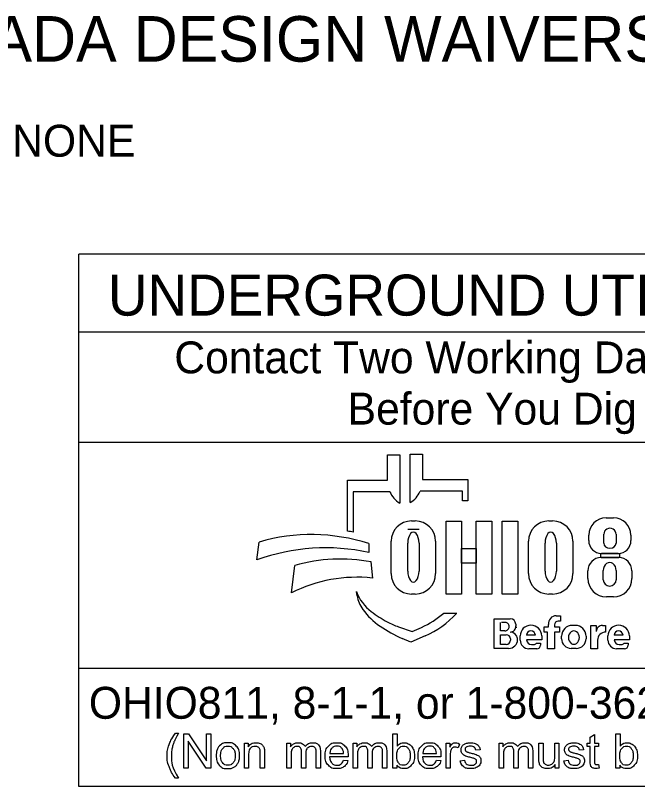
# Model space of a CAD drawing. Extents: x 0 to 34, y 0 to 22.
# Drawn here: x 2.1 to 4.831, y 2.143 to 5.529 of the extents above; entities that cross this region are included whole.
import ezdxf

# ---------------------------------------------------------------- set-up
doc = ezdxf.new("R2010")
doc.units = 0
for name, color, linetype in [('Default', 7, 'Continuous'), ('SH_Data', 7, 'Continuous'), ('SH_Text', 7, 'Continuous')]:
    doc.layers.add(name, color=color, linetype=linetype)

msp = doc.modelspace()

# ---------------------------------------------------------------- linework, layer by layer
at = {"layer": 'SH_Data'}
for p, q in [((2.3775, 2.1428), (2.3775, 4.4803)), ((6.6275, 4.4803), (2.3775, 4.4803)), ((2.3775, 4.1387), (6.6275, 4.1387)), ((2.3775, 3.6553), (6.6275, 3.6553)), ((6.6275, 2.6607), (2.3775, 2.6607)), ((6.6275, 2.1428), (2.3775, 2.1428))]:
    msp.add_line(p, q, dxfattribs=at)
at = {"layer": 'SH_Text'}
for p, q in [((3.7335, 3.4883), (3.7335, 3.5998)), ((3.7335, 3.5998), (3.7872, 3.5998)), ((3.7872, 3.5998), (3.7872, 3.3877)), ((3.8329, 3.39), (3.8329, 3.6021)), ((3.8329, 3.6021), (3.8865, 3.6021)), ((3.8865, 3.6021), (3.8865, 3.4906)), ((3.5576, 3.2644), (3.5576, 3.4883)), ((3.5576, 3.4883), (3.7335, 3.4883)), ((3.8865, 3.4906), (4.0857, 3.4906)), ((4.0857, 3.4906), (4.0857, 3.3968)), ((3.5828, 3.4369), (3.5828, 3.26)), ((3.7439, 3.4369), (3.5828, 3.4369)), ((4.0625, 3.4392), (3.8761, 3.4392)), ((4.0625, 3.3968), (4.0625, 3.4392)), ((4.0857, 3.3968), (4.0625, 3.3968)), ((4.6931, 3.3231), (4.7258, 3.3231)), ((3.8385, 3.3091), (3.8551, 3.3091)), ((4.4416, 3.3091), (4.4581, 3.3091)), ((3.8718, 3.2721), (3.822, 3.2721)), ((4.683, 3.2111), (4.683, 3.2504)), ((4.7371, 3.2504), (4.7371, 3.2111)), ((3.7491, 3.0776), (3.7491, 3.2196)), ((3.9445, 3.2196), (3.9445, 3.0776)), ((4.3521, 3.0776), (4.3521, 3.2196)), ((4.5476, 3.2196), (4.5476, 3.0776)), ((4.6168, 3.2225), (4.6168, 3.2468)), ((4.8022, 3.2468), (4.8022, 3.2225)), ((3.1602, 3.1381), (3.1696, 3.2162)), ((3.6509, 3.2097), (3.6509, 3.1709)), ((3.822, 3.089), (3.822, 3.2114)), ((3.8718, 3.2114), (3.8718, 3.089)), ((4.425, 3.089), (4.425, 3.2114)), ((4.4748, 3.2114), (4.4748, 3.089)), ((4.7462, 3.1665), (4.6728, 3.1665)), ((3.6608, 3.1291), (3.6671, 3.0582)), ((4.671, 3.1482), (4.7483, 3.1482)), ((3.312, 2.9936), (3.3267, 3.1137)), ((4.6131, 3.0563), (4.6131, 3.0903)), ((4.6806, 3.0503), (4.6806, 3.0912)), ((4.7374, 3.0912), (4.7374, 3.0503)), ((4.8062, 3.0903), (4.8062, 3.0563)), ((3.5997, 2.9807), (3.5967, 2.9986)), ((3.8551, 2.9882), (3.8385, 2.9882)), ((4.4581, 2.9882), (4.4416, 2.9882)), ((4.7252, 2.9753), (4.6941, 2.9753)), ((3.98, 2.9048), (4.0375, 2.9048)), ((4.2013, 2.749), (4.2013, 2.8798)), ((4.2013, 2.8798), (4.2725, 2.8798)), ((4.4739, 2.8926), (4.4934, 2.8926)), ((4.4934, 2.8926), (4.4934, 2.8696)), ((3.7816, 2.8444), (3.841, 2.8239)), ((4.2293, 2.8263), (4.2293, 2.8632)), ((4.2545, 2.8632), (4.2332, 2.8632)), ((4.2963, 2.856), (4.2963, 2.8481)), ((4.4213, 2.8212), (4.4213, 2.8442)), ((4.4213, 2.8442), (4.4406, 2.8442)), ((4.4406, 2.8442), (4.4406, 2.8546)), ((4.4667, 2.8526), (4.4667, 2.8442)), ((4.4667, 2.8442), (4.4883, 2.8442)), ((4.4934, 2.8691), (4.4832, 2.8691)), ((4.4883, 2.8442), (4.4883, 2.8212)), ((4.5451, 2.8508), (4.5573, 2.8508)), ((4.6254, 2.7478), (4.6254, 2.8505)), ((4.6254, 2.8505), (4.6499, 2.8505)), ((4.6499, 2.8505), (4.6499, 2.8237)), ((4.6772, 2.8505), (4.691, 2.8505)), ((4.691, 2.8505), (4.691, 2.8209)), ((3.841, 2.8239), (3.8821, 2.8417)), ((4.2487, 2.8263), (4.2293, 2.8263)), ((4.4362, 2.8212), (4.4213, 2.8212)), ((4.4362, 2.7478), (4.4362, 2.8212)), ((4.4883, 2.8212), (4.4667, 2.8212)), ((4.4667, 2.8212), (4.4667, 2.7478)), ((3.835, 2.7769), (3.7976, 2.7934)), ((3.8983, 2.8044), (3.835, 2.7769)), ((4.2293, 2.7669), (4.2293, 2.8097)), ((4.2293, 2.8097), (4.2548, 2.8097)), ((4.2729, 2.7916), (4.2729, 2.7853)), ((4.3043, 2.7887), (4.3043, 2.7884)), ((4.3159, 2.7858), (4.3159, 2.8042)), ((4.3824, 2.8082), (4.3439, 2.8082)), ((4.4104, 2.7866), (4.344, 2.7866)), ((4.4104, 2.8042), (4.4104, 2.7866)), ((4.4973, 2.7922), (4.4973, 2.8029)), ((4.6051, 2.8029), (4.6051, 2.7922)), ((4.6559, 2.786), (4.6559, 2.7478)), ((4.7008, 2.7858), (4.7008, 2.8042)), ((4.7674, 2.8082), (4.7288, 2.8082)), ((4.7953, 2.7866), (4.7289, 2.7866)), ((4.7953, 2.8042), (4.7953, 2.7866)), ((4.265, 2.749), (4.2013, 2.749)), ((4.2546, 2.7669), (4.2293, 2.7669)), ((4.3892, 2.7478), (4.3538, 2.7478)), ((4.3649, 2.7673), (4.379, 2.7673)), ((4.3876, 2.7729), (4.4045, 2.7729)), ((4.4045, 2.7729), (4.4045, 2.7631)), ((4.4667, 2.7478), (4.4362, 2.7478)), ((4.5623, 2.7494), (4.5401, 2.7494)), ((4.6559, 2.7478), (4.6254, 2.7478)), ((4.7742, 2.7478), (4.7388, 2.7478)), ((4.7498, 2.7673), (4.7639, 2.7673)), ((4.7725, 2.7729), (4.7894, 2.7729)), ((4.7894, 2.7729), (4.7894, 2.7631))]:
    msp.add_line(p, q, dxfattribs=at)
for points in [[(3.991, 3.3081), (4.0589, 3.3081), (4.0589, 2.9881), (3.991, 2.9881)], [(4.1231, 3.3081), (4.1911, 3.3081), (4.1911, 2.9881), (4.1231, 2.9881)], [(4.2364, 3.3081), (4.3052, 3.3081), (4.3052, 2.9881), (4.2364, 2.9881)], [(4.0589, 3.1882), (4.1231, 3.1882), (4.1231, 3.1242), (4.0589, 3.1242)], [(4.6706, 3.1665), (4.7523, 3.1665), (4.7523, 3.1481), (4.6706, 3.1481)]]:
    msp.add_lwpolyline(points, close=True, dxfattribs=at)
for points in [[(2.8021, 2.3766), (2.8153, 2.3766)], [(2.8389, 2.2239), (2.8389, 2.3741), (2.8592, 2.3741), (2.9382, 2.2561), (2.9382, 2.3741), (2.9572, 2.3741), (2.9572, 2.2239), (2.9369, 2.2239), (2.8579, 2.3419), (2.8579, 2.2239), (2.8389, 2.2239)], [(3.7743, 2.2239), (3.7573, 2.2239), (3.7573, 2.3741), (3.7757, 2.3741), (3.7757, 2.3206)], [(4.6233, 2.2558), (4.6233, 2.3185), (4.6097, 2.3185), (4.6097, 2.3328), (4.6233, 2.3328), (4.6233, 2.3597), (4.6417, 2.3708), (4.6417, 2.3328), (4.6601, 2.3328), (4.6601, 2.3185), (4.6417, 2.3185), (4.6417, 2.2547)], [(4.7534, 2.2239), (4.7363, 2.2239), (4.7363, 2.3741), (4.7548, 2.3741), (4.7548, 2.3206)], [(3.1048, 2.2239), (3.1048, 2.3328), (3.1214, 2.3328), (3.1214, 2.3173)], [(3.2912, 2.2239), (3.2912, 2.3328), (3.3077, 2.3328), (3.3077, 2.3174)], [(3.5826, 2.2239), (3.5826, 2.3328), (3.5991, 2.3328), (3.5991, 2.3174)], [(3.9904, 2.2239), (3.9904, 2.3328), (4.007, 2.3328), (4.007, 2.3163)], [(4.0495, 2.3293), (4.043, 2.3122)], [(4.1394, 2.3046), (4.1213, 2.3022)], [(4.2236, 2.2239), (4.2236, 2.3328), (4.2401, 2.3328), (4.2401, 2.3174)], [(4.3979, 2.2654), (4.3979, 2.3328), (4.4164, 2.3328), (4.4164, 2.2724)], [(4.4676, 2.2745), (4.4676, 2.3328), (4.4861, 2.3328), (4.4861, 2.2239), (4.4696, 2.2239)], [(4.594, 2.3046), (4.5759, 2.3022)], [(3.1233, 2.2833), (3.1233, 2.2239), (3.1048, 2.2239)], [(3.1932, 2.2908), (3.1932, 2.2239), (3.1748, 2.2239), (3.1748, 2.2901)], [(3.3097, 2.2803), (3.3097, 2.2239), (3.2912, 2.2239)], [(3.3743, 2.2871), (3.3743, 2.2239), (3.3559, 2.2239), (3.3559, 2.2946)], [(3.4388, 2.2986), (3.4388, 2.2239), (3.4203, 2.2239), (3.4203, 2.2924)], [(3.56, 2.2736), (3.4788, 2.2736)], [(3.4799, 2.2887), (3.5406, 2.2887)], [(3.601, 2.2803), (3.601, 2.2239), (3.5826, 2.2239)], [(3.6657, 2.2871), (3.6657, 2.2239), (3.6473, 2.2239), (3.6473, 2.2946)], [(3.7301, 2.2986), (3.7301, 2.2239), (3.7117, 2.2239), (3.7117, 2.2924)], [(3.968, 2.2736), (3.8868, 2.2736)], [(3.8879, 2.2887), (3.9486, 2.2887)], [(4.0088, 2.2809), (4.0088, 2.2239), (3.9904, 2.2239)], [(4.242, 2.2803), (4.242, 2.2239), (4.2236, 2.2239)], [(4.3067, 2.2871), (4.3067, 2.2239), (4.2883, 2.2239), (4.2883, 2.2946)], [(4.3711, 2.2986), (4.3711, 2.2239), (4.3527, 2.2239), (4.3527, 2.2924)], [(3.5404, 2.2591), (3.5595, 2.2567)], [(3.7743, 2.2375), (3.7743, 2.2239)], [(3.9484, 2.2591), (3.9675, 2.2567)], [(4.053, 2.2564), (4.0712, 2.2593)], [(4.4696, 2.2239), (4.4696, 2.24)], [(4.5076, 2.2564), (4.5258, 2.2593)], [(4.6601, 2.2404), (4.6628, 2.2241)], [(4.7534, 2.2375), (4.7534, 2.2239)], [(2.8153, 2.1798), (2.8021, 2.1798)]]:
    msp.add_lwpolyline(points, dxfattribs=at)
for centre, radius, start, end in [((3.8353, 3.4736), 0.0985, 201.9296, 240.7469), ((3.7847, 3.476), 0.0985, 299.2531, 338.0704), ((4.6931, 3.2468), 0.0763, 90, 180), ((4.7258, 3.2468), 0.0763, 0, 90), ((3.8385, 3.2196), 0.0895, 90, 180), ((3.8551, 3.2196), 0.0895, 0, 90), ((4.4416, 3.2196), 0.0895, 90, 180), ((4.4581, 3.2196), 0.0895, 0, 90), ((3.4295, 2.4554), 0.8191, 79.2074, 81.0007), ((3.3997, 2.4302), 0.8191, 72.1402, 106.3144), ((4.6728, 3.2225), 0.056, 180, 270), ((4.7462, 3.2225), 0.056, 270, 0), ((3.4628, 2.2991), 0.8919, 77.8238, 109.8274), ((3.5267, 2.4094), 0.7322, 79.44, 105.8467), ((4.671, 3.0903), 0.0579, 90, 180), ((4.7483, 3.0903), 0.0579, 0, 90), ((3.5987, 2.4262), 0.6357, 83.8248, 116.8021), ((3.8385, 3.0776), 0.0895, 180, 270), ((3.8551, 3.0776), 0.0895, 270, 0), ((4.4416, 3.0776), 0.0895, 180, 270), ((4.4581, 3.0776), 0.0895, 270, 0), ((4.6941, 3.0563), 0.081, 180, 270), ((4.7252, 3.0563), 0.081, 270, 0), ((3.7841, 3.0707), 0.2008, 201.0457, 232.5314), ((3.741, 3.0048), 0.1433, 189.6817, 216.0884), ((3.8747, 3.1022), 0.3088, 216.0884, 235.7167), ((3.9766, 3.3219), 0.5173, 232.5314, 241.794), ((3.7387, 3.1722), 0.3602, 293.4582, 312.0712), ((3.7387, 3.1722), 0.401, 293.4582, 317.8286), ((4.2725, 2.856), 0.0238, 0, 90), ((4.4739, 2.859), 0.0335, 90, 187.5187), ((4.0412, 3.3465), 0.6044, 235.7167, 246.2325), ((3.8914, 3.1631), 0.3371, 241.794, 250.9821), ((4.2487, 2.845), 0.0187, 270, 2.0582), ((4.2505, 2.8463), 0.0169, 357.8325, 90), ((4.2721, 2.8453), 0.0243, 270, 6.6529), ((4.3631, 2.8042), 0.0473, 0, 180), ((4.4832, 2.8526), 0.0165, 90, 180), ((4.5451, 2.8029), 0.0478, 90, 180), ((4.5573, 2.8029), 0.0478, 0, 90), ((4.6768, 2.8237), 0.0269, 89.2449, 180), ((4.7481, 2.8042), 0.0473, 0, 180), ((4.2722, 2.7889), 0.0321, 4.0748, 90), ((4.2827, 2.8438), 0.0175, 347.4023, 0), ((4.3632, 2.8072), 0.0193, 2.9632, 177.0368), ((4.6908, 2.786), 0.0349, 89.6033, 180), ((4.7481, 2.8072), 0.0193, 2.9632, 177.0368), ((4.2546, 2.7853), 0.0184, 270, 0), ((4.2548, 2.7916), 0.0181, 0, 90), ((4.265, 2.7884), 0.0393, 270, 0), ((4.2714, 2.7887), 0.033, 0, 11.7502), ((4.3538, 2.7858), 0.038, 180, 270), ((4.3649, 2.7883), 0.021, 184.827, 270), ((4.5401, 2.7922), 0.0428, 180, 270), ((4.5623, 2.7922), 0.0428, 270, 0), ((4.7388, 2.7858), 0.038, 180, 270), ((4.7498, 2.7883), 0.021, 184.827, 270), ((4.379, 2.7767), 0.00938, 270, 335.9979), ((4.3892, 2.7631), 0.0152, 270, 0), ((4.7639, 2.7767), 0.00938, 270, 335.9979), ((4.7742, 2.7631), 0.0152, 270, 0)]:
    msp.add_arc(centre, radius, start, end, dxfattribs=at)
for centre, major_axis, ratio, start_param, end_param in [((3.8469, 3.2114), (0, 0.0484), 0.514403, 4.712389, 7.853982), ((4.4499, 3.2114), (0, 0.0484), 0.514403, 4.712389, 7.853982), ((4.71, 3.2504), (0.0271, 0), 0.969373, 0, 3.141593), ((4.71, 3.2111), (0.0271, 0), 0.818453, 3.141593, 6.283185), ((4.709, 3.0912), (0, 0.0358), 0.794529, 4.712389, 7.853982), ((3.8469, 3.089), (0, 0.0484), 0.514403, 1.570796, 4.712389), ((4.4499, 3.089), (0, 0.0484), 0.514403, 1.570796, 4.712389), ((4.709, 3.0503), (0.0284, 0), 0.959837, 3.141593, 6.283185), ((4.5517, 2.7976), (0, 0.029), 0.832186, 4.712389, 7.853982), ((4.5517, 2.7976), (0, 0.0302), 0.797287, 1.570796, 4.712389)]:
    msp.add_ellipse(centre, major_axis=major_axis, ratio=ratio, start_param=start_param, end_param=end_param, dxfattribs=at)
for points in [[(2.8021, 2.1798), (2.7869, 2.199), (2.7763, 2.2248), (2.7657, 2.2506), (2.7657, 2.2783), (2.7657, 2.3026), (2.7736, 2.325), (2.7829, 2.3509), (2.8021, 2.3766)], [(2.8153, 2.3766), (2.8029, 2.3553), (2.7989, 2.3462), (2.7927, 2.332), (2.7891, 2.3167), (2.7847, 2.2975), (2.7847, 2.2782), (2.7847, 2.2289), (2.8153, 2.1798)], [(2.9814, 2.2783), (2.9814, 2.3085), (2.9981, 2.3231), (3.0122, 2.3352), (3.0323, 2.3352), (3.0547, 2.3352), (3.069, 2.3205), (3.0832, 2.3058), (3.0832, 2.2799), (3.0832, 2.2589), (3.0769, 2.2469), (3.0706, 2.2348), (3.0586, 2.2282), (3.0466, 2.2215), (3.0323, 2.2215), (3.0095, 2.2215), (2.9954, 2.2362), (2.9814, 2.2508), (2.9814, 2.2783)], [(3.0003, 2.2783), (3.0003, 2.2574), (3.0094, 2.247), (3.0185, 2.2366), (3.0323, 2.2366), (3.046, 2.2366), (3.0551, 2.2471), (3.0642, 2.2575), (3.0642, 2.279), (3.0642, 2.2991), (3.0551, 2.3095), (3.0459, 2.3199), (3.0323, 2.3199), (3.0185, 2.3199), (3.0094, 2.3096), (3.0003, 2.2992), (3.0003, 2.2783)], [(3.1214, 2.3173), (3.1334, 2.3352), (3.156, 2.3352), (3.1659, 2.3352), (3.1741, 2.3316), (3.1823, 2.3281), (3.1864, 2.3224), (3.1905, 2.3166), (3.1922, 2.3087), (3.1932, 2.3036), (3.1932, 2.2908)], [(3.1748, 2.2901), (3.1748, 2.3013), (3.1726, 2.3069), (3.1705, 2.3125), (3.165, 2.3158), (3.1595, 2.3191), (3.1521, 2.3191), (3.1404, 2.3191), (3.1318, 2.3117), (3.1233, 2.3042), (3.1233, 2.2833)], [(3.3077, 2.3174), (3.3128, 2.3254), (3.3214, 2.3303), (3.3299, 2.3352), (3.3407, 2.3352), (3.3528, 2.3352), (3.3606, 2.3301), (3.3683, 2.3251), (3.3715, 2.3161), (3.3844, 2.3352), (3.4051, 2.3352), (3.4213, 2.3352), (3.43, 2.3262), (3.4388, 2.3172), (3.4388, 2.2986)], [(3.3559, 2.2946), (3.3559, 2.3069), (3.3514, 2.313), (3.3469, 2.3191), (3.3366, 2.3191), (3.3288, 2.3191), (3.3222, 2.315), (3.3156, 2.311), (3.3126, 2.3031), (3.3097, 2.2952), (3.3097, 2.2803)], [(3.4203, 2.2924), (3.4203, 2.3035), (3.4185, 2.3083), (3.4168, 2.3132), (3.412, 2.3162), (3.4073, 2.3191), (3.401, 2.3191), (3.3895, 2.3191), (3.3819, 2.3115), (3.3743, 2.3039), (3.3743, 2.2871)], [(3.5595, 2.2567), (3.555, 2.24), (3.5428, 2.2307), (3.5306, 2.2215), (3.5117, 2.2215), (3.4878, 2.2215), (3.4738, 2.2362), (3.4598, 2.2509), (3.4598, 2.2774), (3.4598, 2.3049), (3.474, 2.32), (3.4881, 2.3352), (3.5106, 2.3352), (3.5324, 2.3352), (3.5463, 2.3203), (3.5601, 2.3055), (3.5601, 2.2785), (3.5601, 2.2769), (3.56, 2.2736)], [(3.5406, 2.2887), (3.5394, 2.3025), (3.5337, 2.3094), (3.5249, 2.3201), (3.5108, 2.3201), (3.4981, 2.3201), (3.4894, 2.3115), (3.4808, 2.303), (3.4799, 2.2887)], [(3.5991, 2.3174), (3.6042, 2.3254), (3.6127, 2.3303), (3.6212, 2.3352), (3.6321, 2.3352), (3.6442, 2.3352), (3.6519, 2.3301), (3.6597, 2.3251), (3.6628, 2.3161), (3.6758, 2.3352), (3.6965, 2.3352), (3.7127, 2.3352), (3.7214, 2.3262), (3.7301, 2.3172), (3.7301, 2.2986)], [(3.6473, 2.2946), (3.6473, 2.3069), (3.6428, 2.313), (3.6383, 2.3191), (3.628, 2.3191), (3.6202, 2.3191), (3.6136, 2.315), (3.607, 2.311), (3.604, 2.3031), (3.601, 2.2952), (3.601, 2.2803)], [(3.7117, 2.2924), (3.7117, 2.3035), (3.7099, 2.3083), (3.7081, 2.3132), (3.7034, 2.3162), (3.6987, 2.3191), (3.6923, 2.3191), (3.6809, 2.3191), (3.6733, 2.3115), (3.6657, 2.3039), (3.6657, 2.2871)], [(3.7741, 2.2792), (3.7741, 2.2596), (3.7794, 2.2509), (3.7881, 2.2366), (3.8029, 2.2366), (3.815, 2.2366), (3.8238, 2.2471), (3.8326, 2.2576), (3.8326, 2.2784), (3.8326, 2.2998), (3.8241, 2.3099), (3.8157, 2.3201), (3.8038, 2.3201), (3.7917, 2.3201), (3.7829, 2.3096), (3.7741, 2.299), (3.7741, 2.2792)], [(3.7757, 2.3206), (3.7874, 2.3352), (3.8055, 2.3352), (3.8155, 2.3352), (3.8245, 2.3311), (3.8335, 2.3271), (3.8392, 2.3198), (3.845, 2.3124), (3.8483, 2.3021), (3.8516, 2.2918), (3.8516, 2.28), (3.8516, 2.252), (3.8378, 2.2368), (3.8239, 2.2215), (3.8046, 2.2215), (3.7853, 2.2215), (3.7743, 2.2375)], [(3.9675, 2.2567), (3.963, 2.24), (3.9508, 2.2307), (3.9386, 2.2215), (3.9196, 2.2215), (3.8958, 2.2215), (3.8818, 2.2362), (3.8678, 2.2509), (3.8678, 2.2774), (3.8678, 2.3049), (3.882, 2.32), (3.8961, 2.3352), (3.9186, 2.3352), (3.9404, 2.3352), (3.9543, 2.3203), (3.9681, 2.3055), (3.9681, 2.2785), (3.9681, 2.2769), (3.968, 2.2736)], [(3.9486, 2.2887), (3.9474, 2.3025), (3.9417, 2.3094), (3.9328, 2.3201), (3.9188, 2.3201), (3.9061, 2.3201), (3.8974, 2.3115), (3.8888, 2.303), (3.8879, 2.2887)], [(4.007, 2.3163), (4.0133, 2.3278), (4.0187, 2.3315), (4.0241, 2.3352), (4.0305, 2.3352), (4.0398, 2.3352), (4.0495, 2.3293)], [(4.043, 2.3122), (4.0363, 2.3162), (4.0295, 2.3162), (4.0235, 2.3162), (4.0187, 2.3125), (4.0139, 2.3089), (4.0119, 2.3024), (4.0088, 2.2926), (4.0088, 2.2809)], [(4.1213, 2.3022), (4.1201, 2.3106), (4.1142, 2.3153), (4.1083, 2.3201), (4.0975, 2.3201), (4.0848, 2.3201), (4.0794, 2.3159), (4.0739, 2.3116), (4.0739, 2.306), (4.0739, 2.3024), (4.0762, 2.2995), (4.0785, 2.2966), (4.0833, 2.2946), (4.086, 2.2936), (4.0996, 2.2899), (4.1192, 2.2847), (4.1269, 2.2813), (4.1347, 2.278), (4.1391, 2.2717), (4.1435, 2.2653), (4.1435, 2.2559), (4.1435, 2.2467), (4.1381, 2.2386), (4.1327, 2.2304), (4.1226, 2.226), (4.1124, 2.2215), (4.0996, 2.2215), (4.0784, 2.2215), (4.0672, 2.2303), (4.0561, 2.2391), (4.053, 2.2564)], [(4.0712, 2.2593), (4.0727, 2.2483), (4.0798, 2.2425), (4.0868, 2.2366), (4.0995, 2.2366), (4.1122, 2.2366), (4.1184, 2.2418), (4.1245, 2.247), (4.1245, 2.254), (4.1245, 2.2602), (4.1191, 2.2638), (4.1153, 2.2663), (4.1002, 2.2701), (4.0799, 2.2752), (4.072, 2.2789), (4.0642, 2.2827), (4.0601, 2.2893), (4.0561, 2.2959), (4.0561, 2.3038), (4.0561, 2.3111), (4.0594, 2.3173), (4.0628, 2.3235), (4.0685, 2.3276), (4.0728, 2.3308), (4.0803, 2.333), (4.0877, 2.3352), (4.0962, 2.3352), (4.109, 2.3352), (4.1187, 2.3315), (4.1284, 2.3278), (4.133, 2.3215), (4.1377, 2.3152), (4.1394, 2.3046)], [(4.2401, 2.3174), (4.2452, 2.3254), (4.2537, 2.3303), (4.2622, 2.3352), (4.2731, 2.3352), (4.2852, 2.3352), (4.2929, 2.3301), (4.3007, 2.3251), (4.3038, 2.3161), (4.3168, 2.3352), (4.3375, 2.3352), (4.3537, 2.3352), (4.3624, 2.3262), (4.3711, 2.3172), (4.3711, 2.2986)], [(4.2883, 2.2946), (4.2883, 2.3069), (4.2838, 2.313), (4.2793, 2.3191), (4.269, 2.3191), (4.2612, 2.3191), (4.2546, 2.315), (4.248, 2.311), (4.245, 2.3031), (4.242, 2.2952), (4.242, 2.2803)], [(4.3527, 2.2924), (4.3527, 2.3035), (4.3509, 2.3083), (4.3491, 2.3132), (4.3444, 2.3162), (4.3397, 2.3191), (4.3333, 2.3191), (4.3219, 2.3191), (4.3143, 2.3115), (4.3067, 2.3039), (4.3067, 2.2871)], [(4.5759, 2.3022), (4.5747, 2.3106), (4.5688, 2.3153), (4.5629, 2.3201), (4.5521, 2.3201), (4.5394, 2.3201), (4.5339, 2.3159), (4.5285, 2.3116), (4.5285, 2.306), (4.5285, 2.3024), (4.5308, 2.2995), (4.533, 2.2966), (4.5378, 2.2946), (4.5406, 2.2936), (4.5542, 2.2899), (4.5737, 2.2847), (4.5815, 2.2813), (4.5893, 2.278), (4.5937, 2.2717), (4.5981, 2.2653), (4.5981, 2.2559), (4.5981, 2.2467), (4.5927, 2.2386), (4.5873, 2.2304), (4.5772, 2.226), (4.567, 2.2215), (4.5542, 2.2215), (4.5329, 2.2215), (4.5218, 2.2303), (4.5107, 2.2391), (4.5076, 2.2564)], [(4.5258, 2.2593), (4.5273, 2.2483), (4.5343, 2.2425), (4.5414, 2.2366), (4.554, 2.2366), (4.5668, 2.2366), (4.5729, 2.2418), (4.5791, 2.247), (4.5791, 2.254), (4.5791, 2.2602), (4.5736, 2.2638), (4.5698, 2.2663), (4.5548, 2.2701), (4.5345, 2.2752), (4.5266, 2.2789), (4.5188, 2.2827), (4.5147, 2.2893), (4.5107, 2.2959), (4.5107, 2.3038), (4.5107, 2.3111), (4.514, 2.3173), (4.5173, 2.3235), (4.5231, 2.3276), (4.5274, 2.3308), (4.5348, 2.333), (4.5423, 2.3352), (4.5508, 2.3352), (4.5636, 2.3352), (4.5733, 2.3315), (4.583, 2.3278), (4.5876, 2.3215), (4.5922, 2.3152), (4.594, 2.3046)], [(4.7532, 2.2792), (4.7532, 2.2596), (4.7585, 2.2509), (4.7672, 2.2366), (4.782, 2.2366), (4.7941, 2.2366), (4.8029, 2.2471), (4.8116, 2.2576), (4.8116, 2.2784), (4.8116, 2.2998), (4.8032, 2.3099), (4.7948, 2.3201), (4.7828, 2.3201), (4.7708, 2.3201), (4.762, 2.3096), (4.7532, 2.299), (4.7532, 2.2792)], [(4.7548, 2.3206), (4.7664, 2.3352), (4.7846, 2.3352), (4.7946, 2.3352), (4.8036, 2.3311), (4.8125, 2.3271), (4.8183, 2.3198), (4.8241, 2.3124), (4.8274, 2.3021), (4.8306, 2.2918), (4.8306, 2.28), (4.8306, 2.252), (4.8168, 2.2368), (4.803, 2.2215), (4.7836, 2.2215), (4.7644, 2.2215), (4.7534, 2.2375)], [(3.4788, 2.2736), (3.4799, 2.2557), (3.489, 2.2462), (3.4981, 2.2366), (3.5117, 2.2366), (3.5219, 2.2366), (3.5291, 2.242), (3.5362, 2.2473), (3.5404, 2.2591)], [(3.8868, 2.2736), (3.8879, 2.2557), (3.897, 2.2462), (3.9061, 2.2366), (3.9197, 2.2366), (3.9299, 2.2366), (3.937, 2.242), (3.9442, 2.2473), (3.9484, 2.2591)], [(4.4164, 2.2724), (4.4164, 2.258), (4.4175, 2.253), (4.4192, 2.2457), (4.4249, 2.2416), (4.4305, 2.2374), (4.4388, 2.2374), (4.4471, 2.2374), (4.4543, 2.2417), (4.4616, 2.2459), (4.4646, 2.2533), (4.4676, 2.2606), (4.4676, 2.2745)], [(4.4696, 2.24), (4.4569, 2.2215), (4.4351, 2.2215), (4.4255, 2.2215), (4.4171, 2.2252), (4.4088, 2.2289), (4.4047, 2.2345), (4.4007, 2.2401), (4.3991, 2.2482), (4.3979, 2.2536), (4.3979, 2.2654)], [(4.6628, 2.2241), (4.655, 2.2224), (4.6488, 2.2224), (4.6388, 2.2224), (4.6333, 2.2256), (4.6278, 2.2288), (4.6255, 2.234), (4.6233, 2.2392), (4.6233, 2.2558)], [(4.6417, 2.2547), (4.6417, 2.2468), (4.6427, 2.2445), (4.6436, 2.2423), (4.6458, 2.2409), (4.648, 2.2396), (4.6521, 2.2396), (4.6551, 2.2396), (4.6601, 2.2404)]]:
    msp.add_open_spline(points, degree=3, dxfattribs=at)

# ---------------------------------------------------------------- texts
at = {"layer": 'Default'}
msp.add_text('NONE', height=0.14, dxfattribs=at).set_placement((2.0853, 4.9084))
at = {"layer": 'SH_Text'}
for s, height, p in [('ADA DESIGN WAIVERS', 0.2, (1.9944, 5.3256)), ('UNDERGROUND UTILITIES', 0.18, (2.5057, 4.2106)), ('Contact Two Working Days', 0.14, (2.7972, 3.9571)), ('Before You Dig', 0.14, (3.5583, 3.7321)), ('OHIO811, 8-1-1, or 1-800-362-2764', 0.14, (2.422, 2.4406))]:
    msp.add_text(s, height=height, dxfattribs=at).set_placement(p)

doc.saveas('drawing.dxf')
